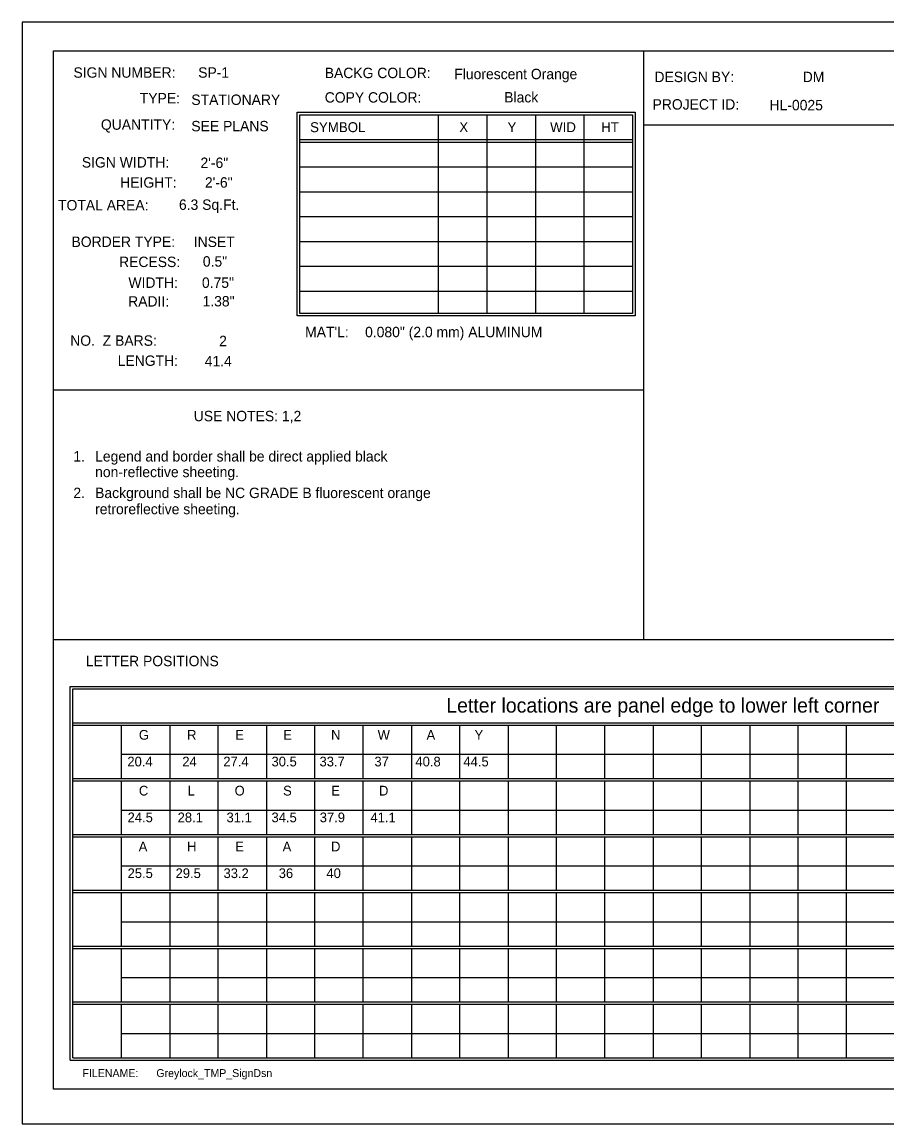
# Model space of a CAD drawing. Extents: x 1788.1 to 1851.2, y 237.2 to 283.4.
# Drawn here: x 1788.1 to 1804.46, y 262.55 to 283.41 of the extents above; entities that cross this region are included whole.
import ezdxf

# ---------------------------------------------------------------- set-up
doc = ezdxf.new("R2010")
doc.units = 0
for name, color, linetype in [('Old_Level_2', 7, 'Continuous'), ('Old_Level_3', 7, 'Continuous'), ('Old_Level_7', 7, 'Continuous'), ('Sheet Plot Border Outside CELL', 7, 'Continuous')]:
    doc.layers.add(name, color=color, linetype=linetype)

msp = doc.modelspace()

# ---------------------------------------------------------------- linework, layer by layer
at = {"layer": 'Old_Level_2'}
for p, q in [((1799.855, 282.859), (1799.855, 271.718)), ((1795.968, 281.65), (1795.968, 277.892)), ((1796.889, 281.65), (1796.889, 277.892)), ((1797.809, 281.65), (1797.809, 277.892)), ((1798.729, 281.65), (1798.729, 277.892)), ((1799.855, 281.461), (1817.019, 281.461)), ((1793.353, 281.181), (1799.649, 281.181)), ((1793.353, 281.134), (1799.649, 281.134)), ((1793.353, 280.664), (1799.649, 280.664)), ((1793.353, 280.194), (1799.649, 280.194)), ((1793.353, 279.725), (1799.649, 279.725)), ((1793.353, 279.255), (1799.649, 279.255)), ((1793.353, 278.785), (1799.649, 278.785)), ((1793.353, 278.315), (1799.649, 278.315)), ((1799.855, 276.442), (1788.693, 276.442)), ((1788.693, 271.718), (1799.855, 271.718)), ((1799.855, 271.718), (1817.019, 271.718)), ((1789.056, 270.146), (1810.834, 270.146)), ((1789.056, 270.1), (1810.834, 270.1)), ((1789.974, 270.1), (1789.974, 269.089)), ((1790.892, 270.1), (1790.892, 269.089)), ((1791.801, 270.1), (1791.801, 269.089)), ((1792.72, 270.1), (1792.72, 269.089)), ((1793.628, 270.1), (1793.628, 269.089)), ((1794.547, 270.1), (1794.547, 269.089)), ((1795.465, 270.1), (1795.465, 269.089)), ((1796.374, 270.1), (1796.374, 269.089)), ((1797.292, 270.1), (1797.292, 269.089)), ((1798.201, 270.1), (1798.201, 269.089)), ((1799.119, 270.1), (1799.119, 269.089)), ((1800.038, 270.1), (1800.038, 269.089)), ((1800.946, 270.1), (1800.946, 269.089)), ((1801.865, 270.1), (1801.865, 269.089)), ((1802.774, 270.1), (1802.774, 269.089)), ((1803.692, 270.1), (1803.692, 269.089)), ((1789.974, 269.548), (1810.834, 269.548)), ((1789.056, 269.089), (1810.834, 269.089)), ((1789.056, 269.043), (1810.834, 269.043)), ((1789.974, 269.043), (1789.974, 268.033)), ((1790.892, 269.043), (1790.892, 268.033)), ((1791.801, 269.043), (1791.801, 268.033)), ((1792.72, 269.043), (1792.72, 268.033)), ((1793.628, 269.043), (1793.628, 268.033)), ((1794.547, 269.043), (1794.547, 268.033)), ((1795.465, 269.043), (1795.465, 268.033)), ((1796.374, 269.043), (1796.374, 268.033)), ((1797.292, 269.043), (1797.292, 268.033)), ((1798.201, 269.043), (1798.201, 268.033)), ((1799.119, 269.043), (1799.119, 268.033)), ((1800.038, 269.043), (1800.038, 268.033)), ((1800.946, 269.043), (1800.946, 268.033)), ((1801.865, 269.043), (1801.865, 268.033)), ((1802.774, 269.043), (1802.774, 268.033)), ((1803.692, 269.043), (1803.692, 268.033)), ((1789.974, 268.492), (1810.834, 268.492)), ((1789.056, 268.033), (1810.834, 268.033)), ((1789.056, 267.987), (1810.834, 267.987)), ((1789.974, 267.987), (1789.974, 266.976)), ((1790.892, 267.987), (1790.892, 266.976)), ((1791.801, 267.987), (1791.801, 266.976)), ((1792.72, 267.987), (1792.72, 266.976)), ((1793.628, 267.987), (1793.628, 266.976)), ((1794.547, 267.987), (1794.547, 266.976)), ((1795.465, 267.987), (1795.465, 266.976)), ((1796.374, 267.987), (1796.374, 266.976)), ((1797.292, 267.987), (1797.292, 266.976)), ((1798.201, 267.987), (1798.201, 266.976)), ((1799.119, 267.987), (1799.119, 266.976)), ((1800.038, 267.987), (1800.038, 266.976)), ((1800.946, 267.987), (1800.946, 266.976)), ((1801.865, 267.987), (1801.865, 266.976)), ((1802.774, 267.987), (1802.774, 266.976)), ((1803.692, 267.987), (1803.692, 266.976)), ((1789.974, 267.436), (1810.834, 267.436)), ((1789.056, 266.976), (1810.834, 266.976)), ((1789.056, 266.93), (1810.834, 266.93)), ((1789.974, 266.93), (1789.974, 265.92)), ((1790.892, 266.93), (1790.892, 265.92)), ((1791.801, 266.93), (1791.801, 265.92)), ((1792.72, 266.93), (1792.72, 265.92)), ((1793.628, 266.93), (1793.628, 265.92)), ((1794.547, 266.93), (1794.547, 265.92)), ((1795.465, 266.93), (1795.465, 265.92)), ((1796.374, 266.93), (1796.374, 265.92)), ((1797.292, 266.93), (1797.292, 265.92)), ((1798.201, 266.93), (1798.201, 265.92)), ((1799.119, 266.93), (1799.119, 265.92)), ((1800.038, 266.93), (1800.038, 265.92)), ((1800.946, 266.93), (1800.946, 265.92)), ((1801.865, 266.93), (1801.865, 265.92)), ((1802.774, 266.93), (1802.774, 265.92)), ((1803.692, 266.93), (1803.692, 265.92)), ((1789.974, 266.379), (1810.834, 266.379)), ((1789.056, 265.92), (1810.834, 265.92)), ((1789.056, 265.92), (1810.834, 265.92)), ((1789.974, 266.037), (1789.974, 265.92)), ((1790.892, 266.037), (1790.892, 265.92)), ((1791.801, 266.037), (1791.801, 265.92)), ((1792.72, 266.037), (1792.72, 265.92)), ((1793.628, 266.037), (1793.628, 265.92)), ((1794.547, 266.037), (1794.547, 265.92)), ((1795.465, 266.037), (1795.465, 265.92)), ((1796.374, 266.037), (1796.374, 265.92)), ((1797.292, 266.037), (1797.292, 265.92)), ((1798.201, 266.037), (1798.201, 265.92)), ((1799.119, 266.037), (1799.119, 265.92)), ((1800.038, 266.037), (1800.038, 265.92)), ((1800.946, 266.037), (1800.946, 265.92)), ((1801.865, 266.037), (1801.865, 265.92)), ((1802.774, 266.037), (1802.774, 265.92)), ((1803.692, 266.037), (1803.692, 265.92)), ((1789.056, 265.874), (1810.834, 265.874)), ((1789.056, 265.874), (1810.834, 265.874)), ((1789.974, 265.874), (1789.974, 264.929)), ((1789.974, 265.874), (1789.974, 264.863)), ((1790.892, 265.874), (1790.892, 264.929)), ((1790.892, 265.874), (1790.892, 264.863)), ((1791.801, 265.874), (1791.801, 264.929)), ((1791.801, 265.874), (1791.801, 264.863)), ((1792.72, 265.874), (1792.72, 264.929)), ((1792.72, 265.874), (1792.72, 264.863)), ((1793.628, 265.874), (1793.628, 264.929)), ((1793.628, 265.874), (1793.628, 264.863)), ((1794.547, 265.874), (1794.547, 264.929)), ((1794.547, 265.874), (1794.547, 264.863)), ((1795.465, 265.874), (1795.465, 264.929)), ((1795.465, 265.874), (1795.465, 264.863)), ((1796.374, 265.874), (1796.374, 264.929)), ((1796.374, 265.874), (1796.374, 264.863)), ((1797.292, 265.874), (1797.292, 264.929)), ((1797.292, 265.874), (1797.292, 264.863)), ((1798.201, 265.874), (1798.201, 264.929)), ((1798.201, 265.874), (1798.201, 264.863)), ((1799.119, 265.874), (1799.119, 264.929)), ((1799.119, 265.874), (1799.119, 264.863)), ((1800.038, 265.874), (1800.038, 264.929)), ((1800.038, 265.874), (1800.038, 264.863)), ((1800.946, 265.874), (1800.946, 264.929)), ((1800.946, 265.874), (1800.946, 264.863)), ((1801.865, 265.874), (1801.865, 264.929)), ((1801.865, 265.874), (1801.865, 264.863)), ((1802.774, 265.874), (1802.774, 264.929)), ((1802.774, 265.874), (1802.774, 264.863)), ((1803.692, 265.874), (1803.692, 264.929)), ((1803.692, 265.874), (1803.692, 264.863)), ((1789.974, 265.323), (1810.834, 265.323)), ((1789.974, 265.323), (1810.834, 265.323)), ((1789.056, 264.863), (1810.834, 264.863)), ((1789.056, 264.863), (1810.834, 264.863)), ((1789.974, 264.981), (1789.974, 264.863)), ((1790.892, 264.981), (1790.892, 264.863)), ((1791.801, 264.981), (1791.801, 264.863)), ((1792.72, 264.981), (1792.72, 264.863)), ((1793.628, 264.981), (1793.628, 264.863)), ((1794.547, 264.981), (1794.547, 264.863)), ((1795.465, 264.981), (1795.465, 264.863)), ((1796.374, 264.981), (1796.374, 264.863)), ((1797.292, 264.981), (1797.292, 264.863)), ((1798.201, 264.981), (1798.201, 264.863)), ((1799.119, 264.981), (1799.119, 264.863)), ((1800.038, 264.981), (1800.038, 264.863)), ((1800.946, 264.981), (1800.946, 264.863)), ((1801.865, 264.981), (1801.865, 264.863)), ((1802.774, 264.981), (1802.774, 264.863)), ((1803.692, 264.981), (1803.692, 264.863)), ((1789.056, 264.817), (1810.834, 264.817)), ((1789.056, 264.817), (1810.834, 264.817)), ((1789.974, 264.817), (1789.974, 263.807)), ((1789.974, 264.817), (1789.974, 263.807)), ((1790.892, 264.817), (1790.892, 263.807)), ((1790.892, 264.817), (1790.892, 263.807)), ((1791.801, 264.817), (1791.801, 263.807)), ((1791.801, 264.817), (1791.801, 263.807)), ((1792.72, 264.817), (1792.72, 263.807)), ((1792.72, 264.817), (1792.72, 263.807)), ((1793.628, 264.817), (1793.628, 263.807)), ((1793.628, 264.817), (1793.628, 263.807)), ((1794.547, 264.817), (1794.547, 263.807)), ((1794.547, 264.817), (1794.547, 263.807)), ((1795.465, 264.817), (1795.465, 263.807)), ((1795.465, 264.817), (1795.465, 263.807)), ((1796.374, 264.817), (1796.374, 263.807)), ((1796.374, 264.817), (1796.374, 263.807)), ((1797.292, 264.817), (1797.292, 263.807)), ((1797.292, 264.817), (1797.292, 263.807)), ((1798.201, 264.817), (1798.201, 263.807)), ((1798.201, 264.817), (1798.201, 263.807)), ((1799.119, 264.817), (1799.119, 263.807)), ((1799.119, 264.817), (1799.119, 263.807)), ((1800.038, 264.817), (1800.038, 263.807)), ((1800.038, 264.817), (1800.038, 263.807)), ((1800.946, 264.817), (1800.946, 263.807)), ((1800.946, 264.817), (1800.946, 263.807)), ((1801.865, 264.817), (1801.865, 263.807)), ((1801.865, 264.817), (1801.865, 263.807)), ((1802.774, 264.817), (1802.774, 263.807)), ((1802.774, 264.817), (1802.774, 263.807)), ((1803.692, 264.817), (1803.692, 263.807)), ((1803.692, 264.817), (1803.692, 263.807)), ((1789.974, 264.266), (1810.834, 264.266)), ((1789.974, 264.266), (1810.834, 264.266)), ((1789.056, 263.807), (1810.834, 263.807)), ((1789.056, 263.807), (1810.834, 263.807)), ((1789.009, 263.761), (1810.834, 263.761)), ((1789.056, 263.761), (1810.834, 263.761))]:
    msp.add_line(p, q, dxfattribs=at)
for points in [[(1788.693, 282.859), (1817.019, 282.859), (1817.019, 263.214), (1788.693, 263.214)], [(1793.305, 281.698), (1799.698, 281.698), (1799.698, 277.845), (1793.305, 277.845)], [(1793.353, 281.65), (1799.649, 281.65), (1799.649, 277.892), (1793.353, 277.892)]]:
    msp.add_lwpolyline(points, close=True, dxfattribs=at)
for points in [[(1789.009, 264.929), (1789.009, 270.834), (1810.834, 270.834)], [(1789.056, 264.929), (1789.056, 270.789), (1810.834, 270.789)], [(1789.009, 263.761), (1789.009, 266.037)], [(1789.056, 263.807), (1789.056, 266.037)]]:
    msp.add_lwpolyline(points, dxfattribs=at)
at = {"layer": 'Sheet Plot Border Outside CELL'}
msp.add_lwpolyline([(1818.269, 283.406), (1788.097, 283.406), (1788.097, 262.552), (1818.269, 262.552)], close=True, dxfattribs=at)

# ---------------------------------------------------------------- texts
at = {"layer": 'Old_Level_2'}
for s, height, p in [('SIGN NUMBER:', 0.19685, (1789.07, 282.352)), ('BACKG COLOR:', 0.19685, (1793.824, 282.344)), ('DESIGN BY:', 0.1969, (1800.062, 282.269)), ('TYPE:', 0.1969, (1790.325, 281.866)), ('COPY COLOR:', 0.19685, (1793.824, 281.881)), ('PROJECT ID:', 0.19685, (1800.026, 281.749)), ('HL-0025', 0.1969, (1802.239, 281.735)), ('QUANTITY:', 0.1969, (1789.589, 281.367)), ('SIGN WIDTH:', 0.19685, (1789.229, 280.652)), ('HEIGHT:', 0.1969, (1789.954, 280.271)), ('TOTAL AREA:', 0.19685, (1788.778, 279.841)), ('BORDER TYPE:', 0.19685, (1789.033, 279.149)), ('RECESS:', 0.1969, (1789.933, 278.769)), ('WIDTH:', 0.1969, (1790.11, 278.375)), ('RADII:', 0.1969, (1790.105, 278.021)), ("MAT'L:", 0.1969, (1793.453, 277.441)), ('NO.  Z BARS:', 0.19685, (1789.009, 277.279)), ('LENGTH:', 0.1969, (1789.907, 276.899)), ('USE NOTES: 1,2', 0.19685, (1791.346, 275.851)), ('1.', 0.1969, (1789.068, 275.089)), ('Legend and border shall be direct applied black      ', 0.19685, (1789.48, 275.089)), ('2.', 0.1969, (1789.068, 274.397)), ('LETTER POSITIONS', 0.19685, (1789.304, 271.215)), ('Letter locations are panel edge to lower left corner', 0.27559, (1796.123, 270.337))]:
    msp.add_text(s, height=height, rotation=360, dxfattribs=at).set_placement(p)
for s, height, p in [('DM', 0.1969, (1802.868, 282.269)), ('SYMBOL', 0.1879, (1793.547, 281.322)), ('X', 0.188, (1796.37, 281.322)), ('Y', 0.188, (1797.281, 281.322)), ('WID', 0.1879, (1798.088, 281.322)), ('HT', 0.1879, (1799.054, 281.322)), ('0.080" (2.0 mm) ALUMINUM', 0.19685, (1794.587, 277.441)), ('non-reflective sheeting.', 0.19685, (1789.48, 274.793)), ('Background shall be NC GRADE B fluorescent orange', 0.19685, (1789.48, 274.397)), ('retroreflective sheeting.', 0.19685, (1789.48, 274.091)), ('G', 0.184, (1790.308, 269.824)), ('R', 0.184, (1791.22, 269.824)), ('E', 0.184, (1792.132, 269.824)), ('E', 0.184, (1793.04, 269.824)), ('N', 0.184, (1793.944, 269.824)), ('W', 0.184, (1794.825, 269.824)), ('A', 0.184, (1795.75, 269.824)), ('Y', 0.184, (1796.658, 269.824)), ('20.4', 0.1837, (1790.09, 269.319)), ('24', 0.1837, (1791.129, 269.319)), ('27.4', 0.1837, (1791.905, 269.319)), ('30.5', 0.1837, (1792.817, 269.319)), ('33.7', 0.1837, (1793.725, 269.319)), ('37', 0.1837, (1794.764, 269.319)), ('40.8', 0.1837, (1795.54, 269.319)), ('44.5', 0.1837, (1796.448, 269.319)), ('C', 0.184, (1790.308, 268.768)), ('L', 0.184, (1791.229, 268.768)), ('O', 0.184, (1792.119, 268.768)), ('S', 0.184, (1793.036, 268.768)), ('E', 0.184, (1793.948, 268.768)), ('D', 0.184, (1794.851, 268.768)), ('24.5', 0.1837, (1790.094, 268.262)), ('28.1', 0.1837, (1791.041, 268.262)), ('31.1', 0.1837, (1791.966, 268.262)), ('34.5', 0.1837, (1792.817, 268.262)), ('37.9', 0.1837, (1793.729, 268.262)), ('41.1', 0.1837, (1794.69, 268.262)), ('A', 0.184, (1790.304, 267.711)), ('H', 0.184, (1791.22, 267.711)), ('E', 0.184, (1792.132, 267.711)), ('A', 0.184, (1793.027, 267.711)), ('D', 0.184, (1793.944, 267.711)), ('25.5', 0.1837, (1790.094, 267.206)), ('29.5', 0.1837, (1791.002, 267.206)), ('33.2', 0.1837, (1791.909, 267.206)), ('36', 0.1837, (1792.953, 267.206)), ('40', 0.1837, (1793.856, 267.206))]:
    msp.add_text(s, height=height, dxfattribs=at).set_placement(p)
at = {"layer": 'Old_Level_3'}
for s, height, p in [('SP-1', 0.1969, (1791.43, 282.352)), ('Fluorescent Orange', 0.19685, (1796.275, 282.324)), ('STATIONARY', 0.1969, (1791.3, 281.837)), ('SEE PLANS', 0.1969, (1791.3, 281.338)), ('2\'-6"', 0.1969, (1791.473, 280.644)), ('2\'-6"', 0.1969, (1791.557, 280.272)), ('6.3 Sq.Ft.', 0.1969, (1791.066, 279.851)), ('INSET', 0.1969, (1791.346, 279.148)), ('0.5"', 0.1969, (1791.518, 278.777)), ('0.75"', 0.1969, (1791.501, 278.375)), ('1.38"', 0.1969, (1791.512, 278.024)), ('2', 0.197, (1791.826, 277.271)), ('41.4', 0.1969, (1791.553, 276.89))]:
    msp.add_text(s, height=height, rotation=360, dxfattribs=at).set_placement(p)
msp.add_text('Black', height=0.1969, dxfattribs=at).set_placement((1797.22, 281.884))
at = {"layer": 'Old_Level_7'}
for s, height, p in [('FILENAME:', 0.1497, (1789.241, 263.44)), ('Greylock_TMP_SignDsn', 0.14974, (1790.638, 263.44))]:
    msp.add_text(s, height=height, rotation=360, dxfattribs=at).set_placement(p)

doc.saveas('drawing.dxf')
